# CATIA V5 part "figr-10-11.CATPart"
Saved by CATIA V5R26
Part number: Part1
Bounding box of the stored display mesh (mm): x 0 to 0, y -100 to 90, z 0 to 33.608
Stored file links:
  D:\_Deepak\CATIA\CATIA V5-6R2016_Deepak\Resources\Part files\Partfiles\c10_catia_v5_6r2016_prt\figr-10-11.CATPart
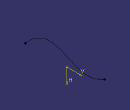
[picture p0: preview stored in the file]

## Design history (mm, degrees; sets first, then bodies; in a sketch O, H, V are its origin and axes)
Set1
  Sketch1 on face of yz-plane, origin (0, 0, 0), H (0, 0, -1), V (0, 1, 0)
    spline S1 through (0, -100) (-30, -20) (-10, 30) (-20, 90)
  Extrude1: Element1 Sketch1, Lim1 0, Lim2 100, Direction face of yz-plane
Body1 (main body)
